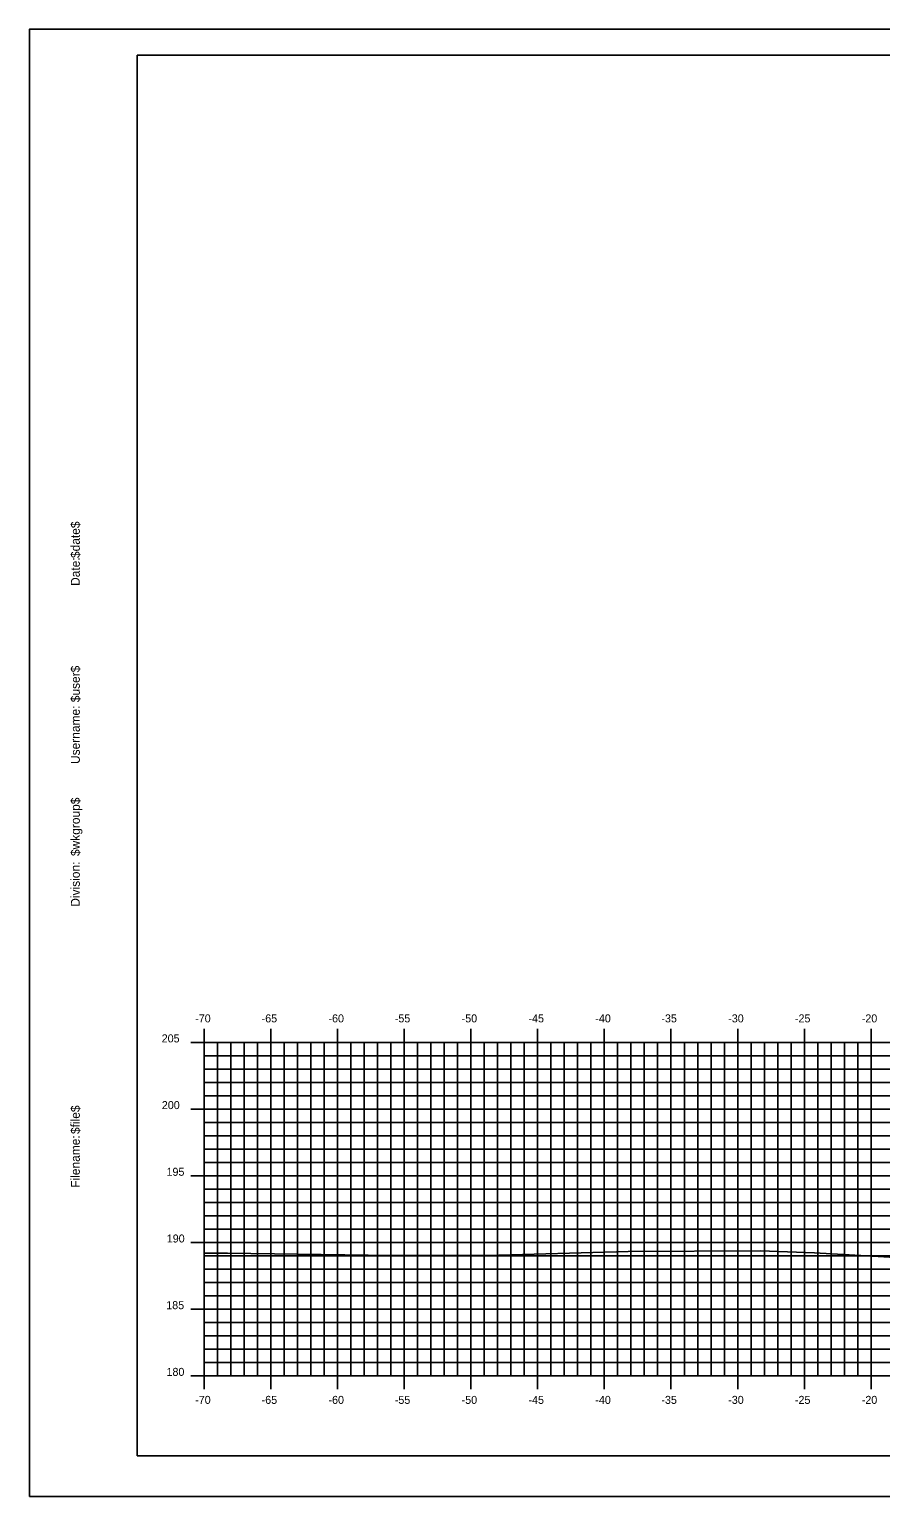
# Model space of a CAD drawing. Extents: x 1724403 to 1724575, y 458501 to 458611.
# Drawn here: x 1724403.3 to 1724467.1, y 458501.2 to 458611.2 of the extents above; entities that cross this region are included whole.
import ezdxf

# ---------------------------------------------------------------- set-up
doc = ezdxf.new("R2010")
doc.units = 0
for name, color, linetype in [('BORDER', 7, 'Continuous'), ('H_V ANNOTATION', 7, 'Continuous'), ('MAJOR', 7, 'Continuous'), ('MINOR', 7, 'Continuous'), ('PLOT BOUNDARY', 7, 'Continuous'), ('S_Roadway_Centerline', 7, 'Continuous')]:
    doc.layers.add(name, color=color, linetype=linetype)

msp = doc.modelspace()

# ---------------------------------------------------------------- linework, layer by layer
at = {"layer": 'BORDER'}
msp.add_lwpolyline([(1724411.39, 458504.25), (1724571.39, 458504.25), (1724571.39, 458609.25), (1724411.39, 458609.25)], close=True, dxfattribs=at)
at = {"layer": 'MAJOR'}
for p, q in [((1724416.39, 458536.26), (1724416.39, 458535.25)), ((1724421.39, 458536.26), (1724421.39, 458535.25)), ((1724426.39, 458536.26), (1724426.39, 458535.25)), ((1724431.39, 458536.26), (1724431.39, 458535.25)), ((1724436.39, 458536.26), (1724436.39, 458535.25)), ((1724441.39, 458536.26), (1724441.39, 458535.25)), ((1724446.39, 458536.26), (1724446.39, 458535.25)), ((1724451.39, 458536.26), (1724451.39, 458535.25)), ((1724456.39, 458536.26), (1724456.39, 458535.25)), ((1724461.39, 458536.26), (1724461.39, 458535.25)), ((1724466.39, 458536.26), (1724466.39, 458535.25)), ((1724415.39, 458535.25), (1724416.39, 458535.25)), ((1724416.39, 458535.25), (1724556.39, 458535.25)), ((1724416.39, 458510.25), (1724416.39, 458535.25)), ((1724416.39, 458510.25), (1724416.39, 458535.25)), ((1724416.39, 458535.25), (1724556.39, 458535.25)), ((1724421.39, 458510.25), (1724421.39, 458535.25)), ((1724426.39, 458510.25), (1724426.39, 458535.25)), ((1724431.39, 458510.25), (1724431.39, 458535.25)), ((1724436.39, 458510.25), (1724436.39, 458535.25)), ((1724441.39, 458510.25), (1724441.39, 458535.25)), ((1724446.39, 458510.25), (1724446.39, 458535.25)), ((1724451.39, 458510.25), (1724451.39, 458535.25)), ((1724456.39, 458510.25), (1724456.39, 458535.25)), ((1724461.39, 458510.25), (1724461.39, 458535.25)), ((1724466.39, 458510.25), (1724466.39, 458535.25)), ((1724415.39, 458530.25), (1724416.39, 458530.25)), ((1724416.39, 458530.25), (1724556.39, 458530.25)), ((1724415.39, 458525.25), (1724416.39, 458525.25)), ((1724416.39, 458525.25), (1724556.39, 458525.25)), ((1724415.39, 458520.25), (1724416.39, 458520.25)), ((1724416.39, 458520.25), (1724556.39, 458520.25)), ((1724415.39, 458515.25), (1724416.39, 458515.25)), ((1724416.39, 458515.25), (1724556.39, 458515.25)), ((1724415.39, 458510.25), (1724416.39, 458510.25)), ((1724416.39, 458510.25), (1724556.39, 458510.25)), ((1724416.39, 458510.25), (1724556.39, 458510.25)), ((1724416.39, 458509.25), (1724416.39, 458510.25)), ((1724421.39, 458509.25), (1724421.39, 458510.25)), ((1724426.39, 458509.25), (1724426.39, 458510.25)), ((1724431.39, 458509.25), (1724431.39, 458510.25)), ((1724436.39, 458509.25), (1724436.39, 458510.25)), ((1724441.39, 458509.25), (1724441.39, 458510.25)), ((1724446.39, 458509.25), (1724446.39, 458510.25)), ((1724451.39, 458509.25), (1724451.39, 458510.25)), ((1724456.39, 458509.25), (1724456.39, 458510.25)), ((1724461.39, 458509.25), (1724461.39, 458510.25)), ((1724466.39, 458509.25), (1724466.39, 458510.25))]:
    msp.add_line(p, q, dxfattribs=at)
at = {"layer": 'MINOR'}
for p, q in [((1724417.39, 458510.25), (1724417.39, 458535.25)), ((1724418.39, 458510.25), (1724418.39, 458535.25)), ((1724419.39, 458510.25), (1724419.39, 458535.25)), ((1724420.39, 458510.25), (1724420.39, 458535.25)), ((1724422.39, 458510.25), (1724422.39, 458535.25)), ((1724423.39, 458510.25), (1724423.39, 458535.25)), ((1724424.39, 458510.25), (1724424.39, 458535.25)), ((1724425.39, 458510.25), (1724425.39, 458535.25)), ((1724427.39, 458510.25), (1724427.39, 458535.25)), ((1724428.39, 458510.25), (1724428.39, 458535.25)), ((1724429.39, 458510.25), (1724429.39, 458535.25)), ((1724430.39, 458510.25), (1724430.39, 458535.25)), ((1724432.39, 458510.25), (1724432.39, 458535.25)), ((1724433.39, 458510.25), (1724433.39, 458535.25)), ((1724434.39, 458510.25), (1724434.39, 458535.25)), ((1724435.39, 458510.25), (1724435.39, 458535.25)), ((1724437.39, 458510.25), (1724437.39, 458535.25)), ((1724438.39, 458510.25), (1724438.39, 458535.25)), ((1724439.39, 458510.25), (1724439.39, 458535.25)), ((1724440.39, 458510.25), (1724440.39, 458535.25)), ((1724442.39, 458510.25), (1724442.39, 458535.25)), ((1724443.39, 458510.25), (1724443.39, 458535.25)), ((1724444.39, 458510.25), (1724444.39, 458535.25)), ((1724445.39, 458510.25), (1724445.39, 458535.25)), ((1724447.39, 458510.25), (1724447.39, 458535.25)), ((1724448.39, 458510.25), (1724448.39, 458535.25)), ((1724449.39, 458510.25), (1724449.39, 458535.25)), ((1724450.39, 458510.25), (1724450.39, 458535.25)), ((1724452.39, 458510.25), (1724452.39, 458535.25)), ((1724453.39, 458510.25), (1724453.39, 458535.25)), ((1724454.39, 458510.25), (1724454.39, 458535.25)), ((1724455.39, 458510.25), (1724455.39, 458535.25)), ((1724457.39, 458510.25), (1724457.39, 458535.25)), ((1724458.39, 458510.25), (1724458.39, 458535.25)), ((1724459.39, 458510.25), (1724459.39, 458535.25)), ((1724460.39, 458510.25), (1724460.39, 458535.25)), ((1724462.39, 458510.25), (1724462.39, 458535.25)), ((1724463.39, 458510.25), (1724463.39, 458535.25)), ((1724464.39, 458510.25), (1724464.39, 458535.25)), ((1724465.39, 458510.25), (1724465.39, 458535.25)), ((1724416.39, 458534.25), (1724556.39, 458534.25)), ((1724416.39, 458534.25), (1724417.39, 458534.25)), ((1724416.39, 458533.25), (1724556.39, 458533.25)), ((1724416.39, 458533.25), (1724417.39, 458533.25)), ((1724416.39, 458532.25), (1724556.39, 458532.25)), ((1724416.39, 458532.25), (1724417.39, 458532.25)), ((1724416.39, 458531.25), (1724556.39, 458531.25)), ((1724416.39, 458531.25), (1724417.39, 458531.25)), ((1724416.39, 458529.25), (1724556.39, 458529.25)), ((1724416.39, 458529.25), (1724417.39, 458529.25)), ((1724416.39, 458528.25), (1724556.39, 458528.25)), ((1724416.39, 458528.25), (1724417.39, 458528.25)), ((1724416.39, 458527.25), (1724556.39, 458527.25)), ((1724416.39, 458527.25), (1724417.39, 458527.25)), ((1724416.39, 458526.25), (1724556.39, 458526.25)), ((1724416.39, 458526.25), (1724417.39, 458526.25)), ((1724416.39, 458524.25), (1724556.39, 458524.25)), ((1724416.39, 458524.25), (1724417.39, 458524.25)), ((1724416.39, 458523.25), (1724556.39, 458523.25)), ((1724416.39, 458523.25), (1724417.39, 458523.25)), ((1724416.39, 458522.25), (1724556.39, 458522.25)), ((1724416.39, 458522.25), (1724417.39, 458522.25)), ((1724416.39, 458521.25), (1724556.39, 458521.25)), ((1724416.39, 458521.25), (1724417.39, 458521.25)), ((1724416.39, 458519.25), (1724556.39, 458519.25)), ((1724416.39, 458519.25), (1724417.39, 458519.25)), ((1724416.39, 458518.25), (1724556.39, 458518.25)), ((1724416.39, 458518.25), (1724417.39, 458518.25)), ((1724416.39, 458517.25), (1724556.39, 458517.25)), ((1724416.39, 458517.25), (1724417.39, 458517.25)), ((1724416.39, 458516.25), (1724556.39, 458516.25)), ((1724416.39, 458516.25), (1724417.39, 458516.25)), ((1724416.39, 458514.25), (1724556.39, 458514.25)), ((1724416.39, 458514.25), (1724417.39, 458514.25)), ((1724416.39, 458513.25), (1724556.39, 458513.25)), ((1724416.39, 458513.25), (1724417.39, 458513.25)), ((1724416.39, 458512.25), (1724556.39, 458512.25)), ((1724416.39, 458512.25), (1724417.39, 458512.25)), ((1724416.39, 458511.25), (1724556.39, 458511.25)), ((1724416.39, 458511.25), (1724417.39, 458511.25))]:
    msp.add_line(p, q, dxfattribs=at)
at = {"layer": 'PLOT BOUNDARY'}
msp.add_lwpolyline([(1724403.3, 458501.2), (1724573.3, 458501.2), (1724573.3, 458611.2), (1724403.3, 458611.2)], close=True, dxfattribs=at)
at = {"layer": 'S_Roadway_Centerline'}
msp.add_lwpolyline([(1724416.39, 458519.45), (1724418.16, 458519.44), (1724428.69, 458519.29), (1724437.6, 458519.27), (1724448.18, 458519.57), (1724458.11, 458519.62), (1724462.15, 458519.48), (1724475.14, 458518.73), (1724482.14, 458518.26), (1724494.46, 458518.11), (1724495.17, 458518.09), (1724496.19, 458518.03), (1724514.14, 458517.02), (1724518.7, 458516.87), (1724526.33, 458516.92), (1724533.95, 458516.69), (1724543.73, 458516.08), (1724551.8, 458515.43), (1724556.39, 458515.3)], dxfattribs=at)

# ---------------------------------------------------------------- texts
at = {"layer": 'BORDER'}
for s, p in [('$date$', (1724407.08, 458571.56)), ('Date:', (1724407.08, 458569.47)), ('$user$', (1724407.08, 458560.75)), ('Username:', (1724407.08, 458556.12)), ('$wkgroup$', (1724407.08, 458549.22)), ('Division:', (1724407.08, 458545.42)), ('$file$', (1724407.08, 458528.38)), ('Filename:', (1724407.08, 458524.35))]:
    msp.add_text(s, height=0.67, rotation=90, dxfattribs=at).set_placement(p)
at = {"layer": 'H_V ANNOTATION'}
for s, p in [('-70', (1724415.73, 458536.75)), ('-65', (1724420.71, 458536.75)), ('-60', (1724425.72, 458536.75)), ('-55', (1724430.69, 458536.75)), ('-50', (1724435.7, 458536.75)), ('-45', (1724440.71, 458536.75)), ('-40', (1724445.72, 458536.75)), ('-35', (1724450.67, 458536.75)), ('-30', (1724455.68, 458536.75)), ('-25', (1724460.68, 458536.75)), ('-20', (1724465.69, 458536.75)), ('205', (1724413.22, 458535.25)), ('200', (1724413.23, 458530.25)), ('195', (1724413.58, 458525.25)), ('190', (1724413.6, 458520.25)), ('185', (1724413.56, 458515.25)), ('180', (1724413.58, 458510.25)), ('-70', (1724415.73, 458508.15)), ('-65', (1724420.71, 458508.15)), ('-60', (1724425.72, 458508.15)), ('-55', (1724430.69, 458508.15)), ('-50', (1724435.7, 458508.15)), ('-45', (1724440.71, 458508.15)), ('-40', (1724445.72, 458508.15)), ('-35', (1724450.67, 458508.15)), ('-30', (1724455.68, 458508.15)), ('-25', (1724460.68, 458508.15)), ('-20', (1724465.69, 458508.15))]:
    msp.add_text(s, height=0.6, dxfattribs=at).set_placement(p)
at = {"layer": 'MAJOR'}
msp.add_text('-', height=0.006, dxfattribs=at).set_placement((1724416.39, 458510.25))

doc.saveas('drawing.dxf')
